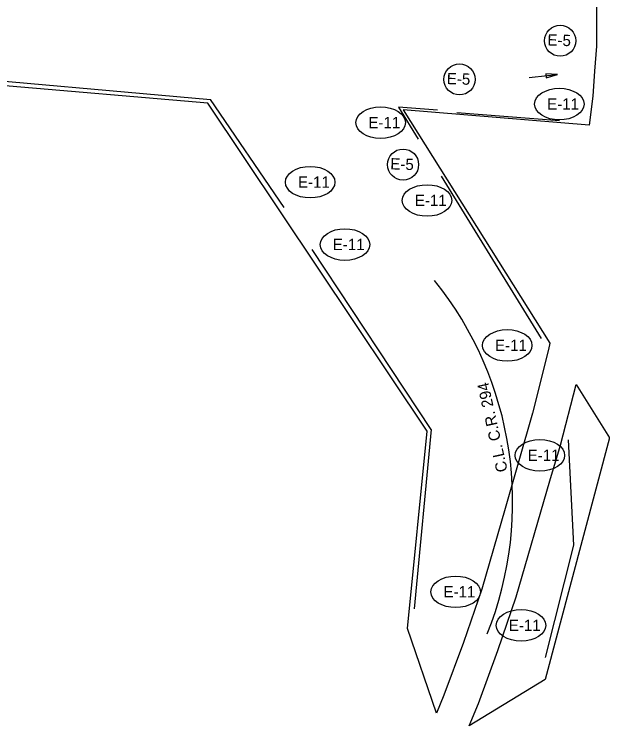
# Model space of a CAD drawing. Extents: x 977239 to 983725, y 1525948 to 1526901.
# Drawn here: x 977523.2 to 977835.8, y 1526058.9 to 1526437.1 of the extents above; entities that cross this region are included whole.
import ezdxf

# ---------------------------------------------------------------- set-up
doc = ezdxf.new("R2010")
doc.units = 0
for name, color, linetype in [('Default', 7, 'Continuous'), ('R_Erosion', 7, 'Continuous'), ('R_Horz Alg', 7, 'Continuous'), ('R_Horz Alg Annot', 7, 'Continuous'), ('R_No Plot', 7, 'Continuous'), ('R_Water', 7, 'Continuous')]:
    doc.layers.add(name, color=color, linetype=linetype)

msp = doc.modelspace()

# ---------------------------------------------------------------- linework, layer by layer
at = {"layer": 'R_Erosion'}
for p, q in [((977666.59, 1526334.39), (977627.5, 1526391.74)), ((977727.35, 1526387.67), (977737.8, 1526370.72)), ((977748.02, 1526386.07), (977727.35, 1526387.67)), ((977812.93, 1526380.49), (977758.28, 1526384.72)), ((977749.92, 1526351.05), (977803.11, 1526264.72)), ((977744.69, 1526216.3), (977681.43, 1526312)), ((977744.69, 1526216.3), (977735.63, 1526121.11)), ((977820.39, 1526154.82), (977817.63, 1526210.86)), ((977805.33, 1526095.16), (977820.39, 1526154.82))]:
    msp.add_line(p, q, dxfattribs=at)
msp.add_lwpolyline([(977344.28, 1526414.51), (977476.25, 1526405.26), (977627.5, 1526391.74)], dxfattribs=at)
for centre in [(977813.2, 1526423.06), (977759.74, 1526402.51), (977729.74, 1526357.18)]:
    msp.add_circle(centre, 8.26, dxfattribs=at)
for centre in [(977812.76, 1526389.36), (977717.83, 1526379.5), (977680.41, 1526347.86), (977742.51, 1526338.13), (977698.89, 1526314.71), (977785.09, 1526261.07), (977802.43, 1526202.63), (977757.7, 1526130.08), (977792.42, 1526112.24)]:
    msp.add_ellipse(centre, major_axis=(13.15, 0), ratio=0.638788, dxfattribs=at)
at = {"layer": 'R_Horz Alg'}
msp.add_arc((977600.14, 1526177.78), 187.85, 338.1108, 38.8689, dxfattribs=at)
at = {"layer": 'R_No Plot'}
for p, q in [((977626.12, 1526389.78), (977247.52, 1526422.58)), ((977742.6, 1526215.45), (977626.12, 1526389.78)), ((977828.64, 1526378.09), (977729.82, 1526386.38)), ((977729.82, 1526386.38), (977807.8, 1526262.36)), ((977821.7, 1526240.25), (977839.49, 1526211.96)), ((977732.09, 1526110.67), (977742.6, 1526215.45)), ((977839.49, 1526211.96), (977805.27, 1526083.44)), ((977747.55, 1526065.67), (977732.09, 1526110.67)), ((977805.27, 1526083.44), (977764.9, 1526058.89))]:
    msp.add_line(p, q, dxfattribs=at)
for points in [[(977798.43, 1526491.13), (977819.99, 1526466.67), (977827.76, 1526455.08), (977832.42, 1526442.76), (977832.49, 1526420.17), (977831.51, 1526406.89), (977830.54, 1526393.59), (977828.64, 1526378.09)], [(977807.8, 1526262.36), (977807.03, 1526258.85), (977798.49, 1526225.09), (977784.06, 1526174.41), (977771.54, 1526131.56), (977761.86, 1526103.17), (977751.33, 1526075.09), (977747.55, 1526065.67)], [(977764.9, 1526058.89), (977769.79, 1526070.81), (977780.08, 1526098.97), (977789.86, 1526127.35), (977807.8, 1526189.03), (977813.36, 1526208.13), (977821.7, 1526240.25)]]:
    msp.add_lwpolyline(points, dxfattribs=at)
for centre in [(977813.2, 1526423.06), (977759.74, 1526402.51), (977729.74, 1526357.18)]:
    msp.add_circle(centre, 8.26, dxfattribs=at)
for centre in [(977812.76, 1526389.36), (977717.83, 1526379.5), (977680.41, 1526347.86), (977742.51, 1526338.13), (977698.89, 1526314.71), (977785.09, 1526261.07), (977802.43, 1526202.63), (977757.7, 1526130.08), (977792.42, 1526112.24)]:
    msp.add_ellipse(centre, major_axis=(13.15, 0), ratio=0.638788, dxfattribs=at)
at = {"layer": 'R_Water'}
for p, q in [((977811.71, 1526405.04), (977805.63, 1526405.49)), ((977805.63, 1526405.49), (977805.85, 1526403.38)), ((977805.85, 1526403.38), (977811.71, 1526405.04))]:
    msp.add_line(p, q, dxfattribs=at)
msp.add_lwpolyline([(977796.79, 1526403.5), (977806.44, 1526404.51), (977811.71, 1526405.04)], dxfattribs=at)

# ---------------------------------------------------------------- texts
at = {"layer": 'Default'}
msp.add_text('C.L. C.R. 294', height=0.12, rotation=278.4899, dxfattribs=at).set_placement((977785.68, 1526206.02))
msp.add_text('C.L. C.R. 294', height=0.12, rotation=278.4899, dxfattribs=at).set_placement((977785.68, 1526206.02))
msp.add_text('C.L. C.R. 294', height=0.12, rotation=278.4899, dxfattribs=at).set_placement((977785.68, 1526206.02))
at = {"layer": 'R_Erosion'}
for p in [(977806.35, 1526420.56), (977752.89, 1526400.01), (977722.89, 1526354.68)]:
    msp.add_text('E-5 ', height=5.999, rotation=358.0901, dxfattribs=at).set_placement(p)
for p in [(977806.26, 1526386.41), (977711.33, 1526376.55), (977673.91, 1526344.91), (977736.01, 1526335.18), (977692.39, 1526311.76), (977778.59, 1526258.12), (977795.94, 1526199.68), (977751.2, 1526127.13), (977785.92, 1526109.29)]:
    msp.add_text('E-11', height=5.999, dxfattribs=at).set_placement(p)
at = {"layer": 'R_Horz Alg Annot'}
msp.add_text('C.L. C.R. 294', height=6, rotation=102.3876, dxfattribs=at).set_placement((977785.38, 1526194.4))

doc.saveas('drawing.dxf')
